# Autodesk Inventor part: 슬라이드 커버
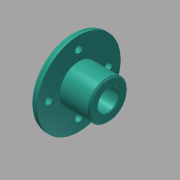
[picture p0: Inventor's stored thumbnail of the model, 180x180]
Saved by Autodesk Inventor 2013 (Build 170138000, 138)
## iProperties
Created: 2015-12
Part Number: 슬라이드 커버
Document SubType Name: Modeling
Designer: mdu
Density: 2.71 g/cm^3
Material: 알루미늄 6061
Mass: 49.5251 g
Surface Area: 80.5945 cm^2
Volume: 18.2749 cm^3
Author: mdu
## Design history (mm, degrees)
sketch "스케치1"
  geometry: L1 (-12.5, 0)-(12.5, 0); L2 (-12.5, 0)-(-12.5, 28); L3 (-12.5, 28)-(-7.5, 28); L4 (-7.5, 28)-(-7.5, 13); L5 (-7.5, 13)-(12.5, 13); L6 (12.5, 13)-(12.5, 0); 2 further points
  constraints: 12 end point, 3 perpendicular, 1 coincident, 1 horizontal, 1 midpoint, 1 parallel
  dimensions: "d1" = 56 diameter of L3 L1; "d2" = 26 diameter of L5 L1; "d5" = 5 distance of L2.end L3.end; "d32" = 20 distance of L4.end L5.end
revolve "회전1" sketch "스케치1" stored, may be unused: angle "d6" = 90 deg
sketch "스케치2" dims "d33" = 40
  geometry: 3 further points
  constraints: 2 vertical alignment, 1 coincident, 2 other
hole "구멍1" sketch "스케치2" at (0, 20) diameter "d8" = 5; stored, may be unused: countersink angle "d12" = 90 deg, drill point angle "d14" = 118 deg; dims "d9" = 6, "d10" = 8, "d11" = 4.4, "d13" = 8
hole "구멍2" diameter "d20" = 14; stored, may be unused: countersink angle "d24" = 90 deg, drill point angle "d26" = 0 deg; dims "d18" = 10, "d19" = 10, "d21" = 6, "d22" = 8, "d23" = 4.4, "d25" = 8
fillet "모깎기1" dims "d27" = 3
chamfer "모따기1" distance "d29" = 1; stored, may be unused: second distance "d30" = 2, angle "d31" = 45 deg
chamfer "모따기2" distance "d35" = 0.5; stored, may be unused: second distance "d36" = 2, angle "d37" = 45 deg
node "솔리드1"
pattern_circular "원형 패턴1" dims angle "d16" = 360 deg
